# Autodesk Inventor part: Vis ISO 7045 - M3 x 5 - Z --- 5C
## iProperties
Created: 2011-01
Part Number: Vis ISO 7045 - M3 x 5 - Z --- 5C
Document SubType Name: Modeling
Designer: eric
Density: 1 g/cm^3
Mass: 0.0802919 g
Surface Area: 1.34852 cm^2
Volume: 0.0802919 cm^3
Author: eric
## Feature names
1. Base1
